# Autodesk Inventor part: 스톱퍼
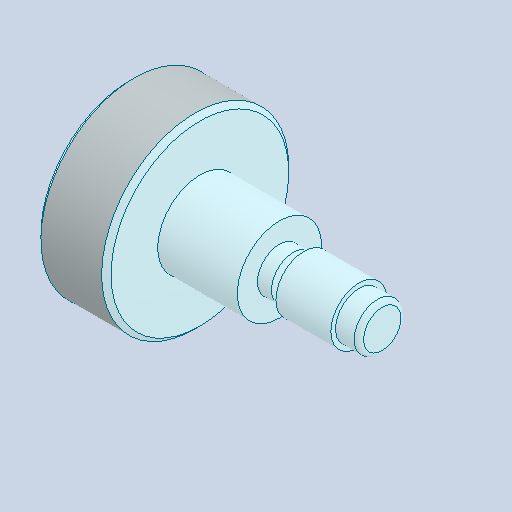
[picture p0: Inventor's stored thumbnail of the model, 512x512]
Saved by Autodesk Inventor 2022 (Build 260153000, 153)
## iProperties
Created: 2024-07
Part Number: 스톱퍼
Material: 강철, 탄소
Document SubType Name: Modeling
Designer: PC-01
Density: 7.85 g/cm^3
Appearance: 기본값
Author: jhkim
Sending System: Autodesk Inventor 2025
Preprocessor: ST-DEVELOPER v20
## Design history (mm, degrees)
feature "솔리드1"
node "솔리드2"
